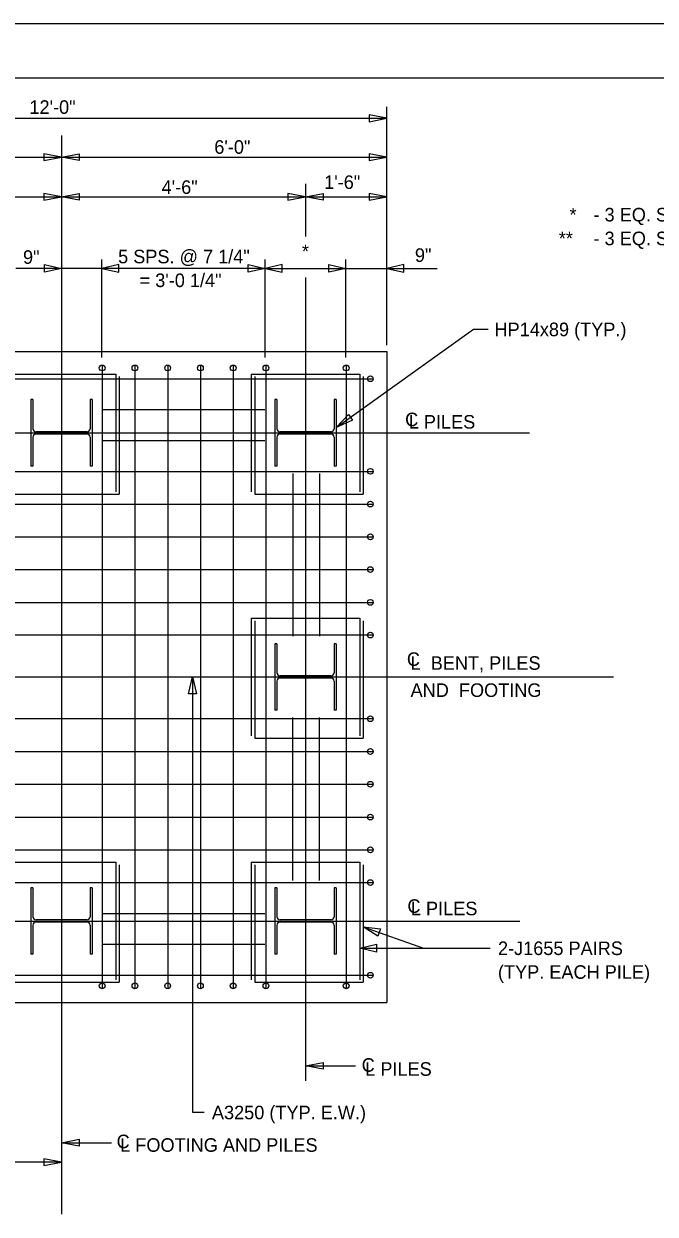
# Model space of a CAD drawing. Extents: x 1970675.2 to 1970711.3, y 796145.2 to 796167.2.
# Drawn here: x 1970693.86 to 1970699.69, y 796156.27 to 796167.25 of the extents above; entities that cross this region are included whole.
import ezdxf

# ---------------------------------------------------------------- set-up
doc = ezdxf.new("R2010")
doc.units = 0
for name, color, linetype in [('BR_AUTO DIMENSION', 7, 'Continuous'), ('BR_BORDER LINES', 7, 'Continuous'), ('BR_CENTER LINES', 7, 'Continuous'), ('BR_CONCRETE', 7, 'Continuous'), ('BR_REBAR', 7, 'Continuous'), ('BR_STRUCTURAL STEEL', 7, 'Continuous'), ('BR_TEXT', 7, 'Continuous'), ('Level 31', 7, 'Continuous')]:
    doc.layers.add(name, color=color, linetype=linetype)

msp = doc.modelspace()

# ---------------------------------------------------------------- linework, layer by layer
at = {"layer": 'BR_AUTO DIMENSION'}
for p, q in [((1970697.212, 796164.284), (1970697.212, 796166.48)), ((1970691.212, 796166.375), (1970697.212, 796166.375)), ((1970691.212, 796166.018), (1970694.212, 796166.018)), ((1970694.212, 796166.018), (1970697.212, 796166.018)), ((1970691.962, 796165.65), (1970694.212, 796165.65)), ((1970694.212, 796165.65), (1970696.462, 796165.65)), ((1970696.462, 796165.65), (1970697.212, 796165.65)), ((1970694.584, 796164.169), (1970694.584, 796165.072)), ((1970696.09, 796164.169), (1970696.09, 796165.072)), ((1970696.834, 796164.169), (1970696.834, 796165.072)), ((1970694.212, 796164.991), (1970693.791, 796164.991)), ((1970694.584, 796164.991), (1970694.212, 796164.991)), ((1970696.09, 796164.991), (1970694.584, 796164.991)), ((1970696.09, 796164.991), (1970696.834, 796164.991)), ((1970696.834, 796164.991), (1970697.212, 796164.991)), ((1970697.212, 796164.991), (1970697.677, 796164.991)), ((1970695.42, 796161.224), (1970695.42, 796157.212)), ((1970696.994, 796158.921), (1970697.55, 796158.723)), ((1970696.962, 796158.723), (1970698.166, 796158.723)), ((1970696.462, 796157.639), (1970696.923, 796157.639)), ((1970695.42, 796157.212), (1970695.527, 796157.212)), ((1970694.212, 796156.93), (1970694.673, 796156.93)), ((1970694.212, 796156.751), (1970693.66, 796156.751))]:
    msp.add_line(p, q, dxfattribs=at)
for points in [[(1970697.049, 796166.344), (1970697.212, 796166.375), (1970697.049, 796166.407)], [(1970694.049, 796165.987), (1970694.212, 796166.018), (1970694.049, 796166.049)], [(1970694.374, 796165.987), (1970694.212, 796166.018), (1970694.374, 796166.049)], [(1970697.049, 796165.987), (1970697.212, 796166.018), (1970697.049, 796166.049)], [(1970694.049, 796165.619), (1970694.212, 796165.65), (1970694.049, 796165.681)], [(1970694.374, 796165.619), (1970694.212, 796165.65), (1970694.374, 796165.681)], [(1970696.299, 796165.619), (1970696.462, 796165.65), (1970696.299, 796165.681)], [(1970696.624, 796165.619), (1970696.462, 796165.65), (1970696.624, 796165.681)], [(1970697.049, 796165.619), (1970697.212, 796165.65), (1970697.049, 796165.681)], [(1970694.056, 796165.027), (1970694.212, 796164.991), (1970694.056, 796164.955)], [(1970694.74, 796165.027), (1970694.584, 796164.991), (1970694.74, 796164.955)], [(1970695.934, 796165.027), (1970696.09, 796164.991), (1970695.934, 796164.955)], [(1970696.246, 796165.027), (1970696.09, 796164.991), (1970696.246, 796164.955)], [(1970696.678, 796165.027), (1970696.834, 796164.991), (1970696.678, 796164.955)], [(1970697.368, 796165.027), (1970697.212, 796164.991), (1970697.368, 796164.955)], [(1970696.895, 796163.593), (1970696.745, 796163.524), (1970696.859, 796163.644)], [(1970695.384, 796161.068), (1970695.42, 796161.224), (1970695.456, 796161.068)], [(1970697.129, 796158.834), (1970696.994, 796158.921), (1970697.153, 796158.902)], [(1970697.118, 796158.687), (1970696.962, 796158.723), (1970697.118, 796158.759)], [(1970696.624, 796157.607), (1970696.462, 796157.639), (1970696.624, 796157.67)], [(1970694.374, 796156.898), (1970694.212, 796156.93), (1970694.374, 796156.961)], [(1970694.049, 796156.72), (1970694.212, 796156.751), (1970694.049, 796156.782)]]:
    msp.add_lwpolyline(points, close=True, dxfattribs=at)
msp.add_lwpolyline([(1970696.745, 796163.524), (1970698.01, 796164.43), (1970698.147, 796164.43)], dxfattribs=at)
at = {"layer": 'BR_BORDER LINES'}
msp.add_line((1970710.736, 796166.746), (1970677.07, 796166.746), dxfattribs=at)
at = {"layer": 'BR_CENTER LINES'}
for p, q in [((1970694.212, 796166.217), (1970694.212, 796156.271)), ((1970696.462, 796165.772), (1970696.462, 796165.285)), ((1970696.462, 796164.907), (1970696.462, 796157.5)), ((1970689.584, 796163.474), (1970698.529, 796163.474)), ((1970689.028, 796161.224), (1970699.302, 796161.224)), ((1970689.584, 796158.974), (1970698.439, 796158.974))]:
    msp.add_line(p, q, dxfattribs=at)
at = {"layer": 'BR_CONCRETE'}
for p, q in [((1970691.212, 796164.224), (1970697.212, 796164.224)), ((1970697.212, 796164.224), (1970697.212, 796158.224)), ((1970691.212, 796158.224), (1970697.212, 796158.224))]:
    msp.add_line(p, q, dxfattribs=at)
at = {"layer": 'BR_REBAR'}
for p, q in [((1970694.587, 796164.099), (1970694.587, 796158.349)), ((1970694.889, 796164.099), (1970694.889, 796158.349)), ((1970695.191, 796164.099), (1970695.191, 796158.349)), ((1970695.493, 796164.099), (1970695.493, 796158.349)), ((1970695.795, 796164.099), (1970695.795, 796158.349)), ((1970696.097, 796164.099), (1970696.097, 796158.349)), ((1970696.837, 796164.099), (1970696.837, 796158.349)), ((1970691.337, 796163.974), (1970697.087, 796163.974)), ((1970693.712, 796164.016), (1970694.712, 796164.016)), ((1970694.712, 796164.016), (1970694.712, 796162.932)), ((1970694.744, 796163.993), (1970694.744, 796162.91)), ((1970695.962, 796164.016), (1970696.962, 796164.016)), ((1970695.962, 796164.016), (1970695.962, 796162.932)), ((1970695.994, 796163.993), (1970695.994, 796162.91)), ((1970696.962, 796164.016), (1970696.962, 796162.932)), ((1970696.994, 796163.993), (1970696.994, 796162.91)), ((1970694.587, 796163.689), (1970696.087, 796163.689)), ((1970694.587, 796163.405), (1970696.087, 796163.405)), ((1970691.337, 796163.12), (1970697.087, 796163.12)), ((1970696.344, 796163.099), (1970696.344, 796161.599)), ((1970696.59, 796163.099), (1970696.59, 796161.599)), ((1970694.212, 796163.016), (1970694.212, 796159.432)), ((1970693.744, 796162.91), (1970694.744, 796162.91)), ((1970695.994, 796162.91), (1970696.994, 796162.91)), ((1970691.337, 796162.818), (1970697.087, 796162.818)), ((1970691.337, 796162.516), (1970697.087, 796162.516)), ((1970691.337, 796162.214), (1970697.087, 796162.214)), ((1970691.337, 796161.912), (1970697.087, 796161.912)), ((1970695.962, 796161.766), (1970696.962, 796161.766)), ((1970695.962, 796161.766), (1970695.962, 796160.682)), ((1970695.994, 796161.743), (1970695.994, 796160.66)), ((1970696.962, 796161.766), (1970696.962, 796160.682)), ((1970696.994, 796161.743), (1970696.994, 796160.66)), ((1970697.087, 796161.61), (1970691.337, 796161.61)), ((1970692.42, 796161.224), (1970696.003, 796161.224)), ((1970697.087, 796160.839), (1970691.337, 796160.839)), ((1970696.344, 796159.349), (1970696.344, 796160.849)), ((1970696.59, 796159.349), (1970696.59, 796160.849)), ((1970695.994, 796160.66), (1970696.994, 796160.66)), ((1970691.337, 796160.537), (1970697.087, 796160.537)), ((1970691.337, 796160.235), (1970697.087, 796160.235)), ((1970691.337, 796159.932), (1970697.087, 796159.932)), ((1970691.337, 796159.63), (1970697.087, 796159.63)), ((1970693.712, 796159.516), (1970694.712, 796159.516)), ((1970694.712, 796159.516), (1970694.712, 796158.432)), ((1970694.744, 796159.493), (1970694.744, 796158.41)), ((1970695.962, 796159.516), (1970696.962, 796159.516)), ((1970695.962, 796159.516), (1970695.962, 796158.432)), ((1970695.994, 796159.493), (1970695.994, 796158.41)), ((1970696.962, 796159.516), (1970696.962, 796158.432)), ((1970696.994, 796159.493), (1970696.994, 796158.41)), ((1970691.337, 796159.328), (1970697.087, 796159.328)), ((1970694.587, 796159.044), (1970696.087, 796159.044)), ((1970694.587, 796158.759), (1970696.087, 796158.759)), ((1970691.337, 796158.474), (1970697.087, 796158.474)), ((1970693.744, 796158.41), (1970694.744, 796158.41)), ((1970695.994, 796158.41), (1970696.994, 796158.41))]:
    msp.add_line(p, q, dxfattribs=at)
for centre in [(1970694.587, 796164.073), (1970694.889, 796164.073), (1970695.191, 796164.073), (1970695.493, 796164.073), (1970695.795, 796164.073), (1970696.097, 796164.073), (1970696.837, 796164.073), (1970697.06, 796163.974), (1970697.06, 796163.12), (1970697.06, 796162.818), (1970697.06, 796162.516), (1970697.06, 796162.214), (1970697.06, 796161.912), (1970697.06, 796161.61), (1970697.06, 796160.839), (1970697.06, 796160.537), (1970697.06, 796160.235), (1970697.06, 796159.932), (1970697.06, 796159.63), (1970697.06, 796159.328), (1970697.06, 796158.474), (1970694.587, 796158.376), (1970694.889, 796158.376), (1970695.191, 796158.376), (1970695.493, 796158.376), (1970695.795, 796158.376), (1970696.097, 796158.376), (1970696.837, 796158.376)]:
    msp.add_circle(centre, 0.0265, dxfattribs=at)
at = {"layer": 'BR_STRUCTURAL STEEL'}
for p, q in [((1970693.928, 796163.781), (1970693.928, 796163.167)), ((1970693.949, 796163.781), (1970693.928, 796163.781)), ((1970693.949, 796163.781), (1970693.949, 796163.513)), ((1970694.475, 796163.781), (1970694.475, 796163.513)), ((1970694.496, 796163.781), (1970694.475, 796163.781)), ((1970694.496, 796163.781), (1970694.496, 796163.167)), ((1970696.178, 796163.781), (1970696.178, 796163.167)), ((1970696.199, 796163.781), (1970696.178, 796163.781)), ((1970696.199, 796163.781), (1970696.199, 796163.513)), ((1970696.725, 796163.781), (1970696.725, 796163.513)), ((1970696.746, 796163.781), (1970696.725, 796163.781)), ((1970696.746, 796163.781), (1970696.746, 796163.167)), ((1970693.949, 796163.436), (1970693.949, 796163.167)), ((1970694.447, 796163.485), (1970693.977, 796163.485)), ((1970694.447, 796163.464), (1970693.977, 796163.464)), ((1970694.475, 796163.436), (1970694.475, 796163.167)), ((1970696.199, 796163.436), (1970696.199, 796163.167)), ((1970696.697, 796163.485), (1970696.227, 796163.485)), ((1970696.697, 796163.464), (1970696.227, 796163.464)), ((1970696.725, 796163.436), (1970696.725, 796163.167)), ((1970693.949, 796163.167), (1970693.928, 796163.167)), ((1970694.496, 796163.167), (1970694.475, 796163.167)), ((1970696.199, 796163.167), (1970696.178, 796163.167)), ((1970696.746, 796163.167), (1970696.725, 796163.167)), ((1970696.178, 796161.531), (1970696.178, 796160.917)), ((1970696.199, 796161.531), (1970696.178, 796161.531)), ((1970696.199, 796161.531), (1970696.199, 796161.263)), ((1970696.725, 796161.531), (1970696.725, 796161.263)), ((1970696.746, 796161.531), (1970696.725, 796161.531)), ((1970696.746, 796161.531), (1970696.746, 796160.917)), ((1970696.697, 796161.235), (1970696.227, 796161.235)), ((1970696.697, 796161.214), (1970696.227, 796161.214)), ((1970696.199, 796161.186), (1970696.199, 796160.917)), ((1970696.725, 796161.186), (1970696.725, 796160.917)), ((1970696.199, 796160.917), (1970696.178, 796160.917)), ((1970696.746, 796160.917), (1970696.725, 796160.917)), ((1970693.928, 796159.281), (1970693.928, 796158.667)), ((1970693.949, 796159.281), (1970693.928, 796159.281)), ((1970693.949, 796159.281), (1970693.949, 796159.013)), ((1970694.475, 796159.281), (1970694.475, 796159.013)), ((1970694.496, 796159.281), (1970694.475, 796159.281)), ((1970694.496, 796159.281), (1970694.496, 796158.667)), ((1970696.178, 796159.281), (1970696.178, 796158.667)), ((1970696.199, 796159.281), (1970696.178, 796159.281)), ((1970696.199, 796159.281), (1970696.199, 796159.013)), ((1970696.725, 796159.281), (1970696.725, 796159.013)), ((1970696.746, 796159.281), (1970696.725, 796159.281)), ((1970696.746, 796159.281), (1970696.746, 796158.667)), ((1970693.949, 796158.936), (1970693.949, 796158.667)), ((1970694.447, 796158.985), (1970693.977, 796158.985)), ((1970694.447, 796158.964), (1970693.977, 796158.964)), ((1970694.475, 796158.936), (1970694.475, 796158.667)), ((1970696.199, 796158.936), (1970696.199, 796158.667)), ((1970696.697, 796158.985), (1970696.227, 796158.985)), ((1970696.697, 796158.964), (1970696.227, 796158.964)), ((1970696.725, 796158.936), (1970696.725, 796158.667)), ((1970693.949, 796158.667), (1970693.928, 796158.667)), ((1970694.496, 796158.667), (1970694.475, 796158.667)), ((1970696.199, 796158.667), (1970696.178, 796158.667)), ((1970696.746, 796158.667), (1970696.725, 796158.667))]:
    msp.add_line(p, q, dxfattribs=at)
for centre, start, end in [((1970693.977, 796163.513), 180, 270), ((1970694.447, 796163.513), 270, 360), ((1970696.227, 796163.513), 180, 270), ((1970696.697, 796163.513), 270, 360), ((1970693.977, 796163.436), 90, 180), ((1970694.447, 796163.436), 360, 90), ((1970696.227, 796163.436), 90, 180), ((1970696.697, 796163.436), 360, 90), ((1970696.227, 796161.263), 180, 270), ((1970696.227, 796161.186), 90, 180), ((1970696.697, 796161.263), 270, 360), ((1970696.697, 796161.186), 360, 90), ((1970693.977, 796159.013), 180, 270), ((1970694.447, 796159.013), 270, 360), ((1970696.227, 796159.013), 180, 270), ((1970696.697, 796159.013), 270, 360), ((1970693.977, 796158.936), 90, 180), ((1970694.447, 796158.936), 360, 90), ((1970696.227, 796158.936), 90, 180), ((1970696.697, 796158.936), 360, 90)]:
    msp.add_arc(centre, 0.0281, start, end, dxfattribs=at)
at = {"layer": 'Level 31'}
msp.add_line((1970711.236, 796167.246), (1970675.236, 796167.246), dxfattribs=at)

# ---------------------------------------------------------------- texts
at = {"layer": 'BR_AUTO DIMENSION'}
for s, p in [('12\'-0"', (1970693.916, 796166.416)), ('6\'-0"', (1970695.621, 796166.048)), ('C', (1970697.381, 796163.536)), ('C', (1970697.397, 796161.326)), ('C', (1970697.402, 796159.049)), ('C', (1970696.98, 796157.584)), ('C', (1970694.72, 796156.879))]:
    msp.add_text(s, height=0.125, dxfattribs=at).set_placement(p)
at = {"layer": 'BR_TEXT'}
for s, p in [('4\'-6"', (1970695.135, 796165.678)), ('1\'-6"', (1970696.634, 796165.724)), ('HP14x89 (TYP.)', (1970698.205, 796164.366)), ('L PILES', (1970697.414, 796163.514)), ('L  BENT, PILES', (1970697.431, 796161.29)), ('AND  FOOTING', (1970697.431, 796161.04)), ('L PILES', (1970697.434, 796159.027)), ('2-J1655 PAIRS', (1970698.237, 796158.66)), ('(TYP. EACH PILE)', (1970698.237, 796158.441)), ('L PILES', (1970697.013, 796157.547)), ('A3250 (TYP. E.W.)', (1970695.599, 796157.146)), ('L FOOTING AND PILES', (1970694.753, 796156.846))]:
    msp.add_text(s, height=0.125, dxfattribs=at).set_placement(p)
for s, p in [('*', (1970698.897, 796165.424)), ('- 3 EQ. SPS. = 1\'-5 3/4"', (1970699.118, 796165.424)), ('**', (1970698.798, 796165.205)), ('- 3 EQ. SPS. = 1\'-8 1/2"', (1970699.118, 796165.205)), ('9"', (1970693.857, 796165.033)), ('5 SPS. @ 7 1/4"', (1970694.734, 796165.038)), ('*', (1970696.429, 796165.086)), ('9"', (1970697.471, 796165.051)), ('= 3\'-0 1/4"', (1970694.932, 796164.819))]:
    msp.add_text(s, height=0.125, rotation=360, dxfattribs=at).set_placement(p)

doc.saveas('drawing.dxf')
